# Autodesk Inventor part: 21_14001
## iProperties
Created: 2006-12
Part Number: 21_14001
Document SubType Name: Modeling
Designer: Andy Moles
Material: Steel
Mass: 22.541 g
Surface Area: 15.9808 cm^2
Volume: 2.87147 cm^3
Density: 7.85 g/cm^3
Author: Andy Moles
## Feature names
1. Extrusion1
2. Revolution1
3. Extrusion2
4. Extrusion3
5. Chamfer1
6. Hole1
7. Chamfer2
